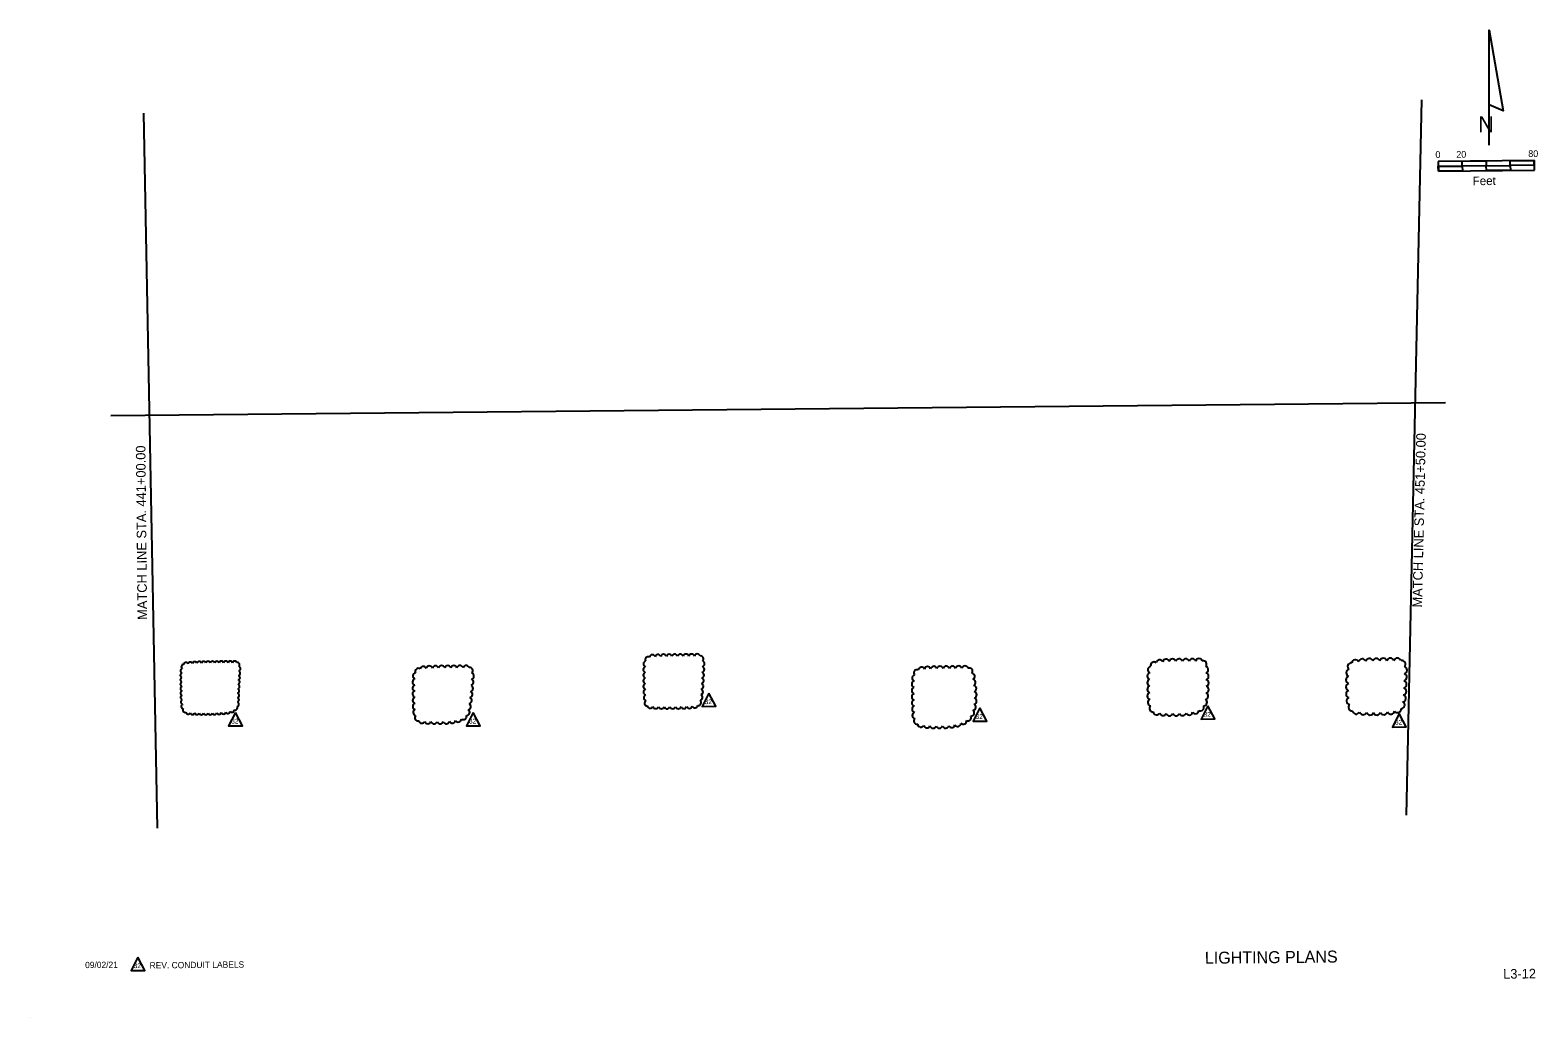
# Model space of a CAD drawing. Extents: x 922408 to 923664, y 636636 to 637460.
import ezdxf

# ---------------------------------------------------------------- set-up
doc = ezdxf.new("R2010")
doc.units = 0
for name, color, linetype in [('ActivePointCell_dp', 7, 'Continuous'), ('AdhocPoint_dp', 7, 'Continuous'), ('Cloud_dp', 7, 'Continuous'), ('MatchLines_dp', 7, 'Continuous'), ('NorthArw_dp', 7, 'Continuous'), ('Scale_dp', 7, 'Continuous'), ('TextLabel', 7, 'Continuous'), ('TextMisc', 7, 'Continuous'), ('TextNotes', 7, 'Continuous'), ('TextShtNo', 7, 'Continuous')]:
    doc.layers.add(name, color=color, linetype=linetype)

msp = doc.modelspace()

# ---------------------------------------------------------------- linework, layer by layer
at = {"layer": 'ActivePointCell_dp'}
msp.add_line((923587.4, 637149.1), (922474.9, 637138.1), dxfattribs=at)
at = {"layer": 'AdhocPoint_dp'}
msp.add_line((922407.6, 636636.3), (922407.6, 636636.3), dxfattribs=at)
at = {"layer": 'Cloud_dp'}
for points in [[(922973.4, 636907), (922967.7, 636895.8), (922979.3, 636896)], [(922578.7, 636890.8), (922573, 636879.6), (922584.6, 636879.7)], [(922776.9, 636890.8), (922771.2, 636879.6), (922782.8, 636879.7)], [(923199.3, 636894.6), (923193.6, 636883.5), (923205.2, 636883.6)], [(923389.3, 636896.5), (923383.7, 636885.3), (923395.2, 636885.5)], [(923548.9, 636889.9), (923543.2, 636878.7), (923554.8, 636878.8)]]:
    msp.add_lwpolyline(points, close=True, dxfattribs=at)
for centre, radius, start, end in [((922535.5, 636928.9), 1.94, 87.0629, 232.0629), ((922537.5, 636930.5), 1.94, 27.4694, 172.4694), ((922541.1, 636931), 1.94, 22.2218, 167.2218), ((922544.8, 636931.2), 1.94, 20.372, 165.372), ((922548.5, 636931.4), 1.94, 19.3363, 164.3363), ((922552.2, 636931.5), 1.94, 18.6507, 163.6507), ((922555.9, 636931.6), 1.94, 18.1729, 163.1729), ((922559.6, 636931.6), 1.94, 18.0695, 163.0695), ((922563.3, 636931.6), 1.94, 18.0695, 163.0695), ((922567, 636931.7), 1.94, 18.0695, 163.0695), ((922570.7, 636931.7), 1.94, 18.0695, 163.0695), ((922574.4, 636931.7), 1.94, 18.0695, 163.0695), ((922578.1, 636931.8), 1.94, 18.0695, 163.0695), ((922580.3, 636930.5), 1.94, 315.3133, 100.3133), ((922581, 636927.3), 1.94, 284.4173, 69.4173), ((922731.2, 636925), 2.68, 56.3128, 201.3128), ((922735.3, 636926.6), 2.68, 22.3621, 167.3621), ((922740.4, 636927), 2.68, 19.9071, 164.9071), ((922745.5, 636927.1), 2.68, 18.7885, 163.7885), ((922750.6, 636927.2), 2.68, 18.1593, 163.1593), ((922755.7, 636927.3), 2.68, 18.0695, 163.0695), ((922760.8, 636927.3), 2.68, 18.0695, 163.0695), ((922765.9, 636927.4), 2.68, 18.0695, 163.0695), ((922771, 636927.4), 2.68, 18.0695, 163.0695), ((922774, 636925.6), 2.68, 314.7185, 99.7185), ((922921.1, 636926.6), 2.46, 106.8525, 251.8525), ((922921.3, 636931.3), 2.46, 105.2115, 250.2115), ((922922.8, 636934.9), 2.46, 64.4078, 209.4078), ((922926.2, 636936.5), 2.46, 21.0985, 166.0985), ((922930.9, 636936.7), 2.46, 19.421, 164.421), ((922935.6, 636936.9), 2.46, 18.6886, 163.6886), ((922940.3, 636936.9), 2.46, 18.2508, 163.2508), ((922944.9, 636937), 2.46, 18.0699, 163.0699), ((922949.6, 636937), 2.46, 18.0695, 163.0695), ((922954.3, 636937.1), 2.46, 18.0695, 163.0695), ((922959, 636937.1), 2.46, 18.0695, 163.0695), ((922963.7, 636937.2), 2.46, 18.0695, 163.0695), ((922966.5, 636935.5), 2.46, 315.3025, 100.3025), ((922967.2, 636926.8), 2.46, 284.525, 69.525), ((922967.4, 636931.5), 2.46, 284.525, 69.525), ((923150.6, 636925.9), 2.73, 24.6638, 169.6638), ((923155.7, 636926.4), 2.73, 20.7187, 165.7187), ((923160.9, 636926.6), 2.73, 19.1288, 164.1288), ((923166.1, 636926.7), 2.73, 18.2398, 163.2398), ((923171.3, 636926.8), 2.73, 18.0695, 163.0695), ((923176.5, 636926.8), 2.73, 18.0695, 163.0695), ((923181.7, 636926.9), 2.73, 18.0695, 163.0695), ((923186.9, 636926.9), 2.73, 18.0695, 163.0695), ((923190.5, 636925.2), 2.73, 326.4662, 111.4662), ((923342.2, 636926.5), 2.88, 100.4246, 245.4246), ((923344.5, 636930.1), 2.88, 50.3955, 195.3955), ((923349.2, 636931.9), 2.88, 25.5069, 170.5069), ((923354.6, 636932.4), 2.88, 21.0103, 166.0103), ((923360, 636932.6), 2.88, 18.8039, 163.8039), ((923365.5, 636932.7), 2.88, 18.0695, 163.0695), ((923371, 636932.8), 2.88, 18.0695, 163.0695), ((923376.5, 636932.8), 2.88, 18.0695, 163.0695), ((923382, 636932.9), 2.88, 18.0695, 163.0695), ((923385.5, 636931), 2.88, 320.4892, 105.4892), ((923386.9, 636926.4), 2.88, 289.0567, 74.0567), ((923509, 636929.1), 3.08, 83.8725, 228.8725), ((923512.4, 636931.8), 3.08, 28.1171, 173.1171), ((923518.1, 636932.5), 3.08, 21.4569, 166.4569), ((923524, 636932.8), 3.08, 19.1108, 164.1108), ((923529.8, 636932.9), 3.08, 18.1025, 163.1025), ((923535.7, 636933), 3.08, 18.0695, 163.0695), ((923541.6, 636933.1), 3.08, 18.0695, 163.0695), ((923547.4, 636933.1), 3.08, 18.0695, 163.0695), ((923551.1, 636931.1), 3.08, 317.9117, 102.9117), ((923552.4, 636926.1), 3.08, 286.0769, 71.0769), ((922534.7, 636921.8), 1.94, 106.9984, 251.9984), ((922534.7, 636918.1), 1.94, 107.5151, 252.5151), ((922534.7, 636914.4), 1.94, 107.8364, 252.8364), ((922534.8, 636925.5), 1.94, 105.9338, 250.9338), ((922580.4, 636916.2), 1.94, 284.4873, 69.4873), ((922580.6, 636919.9), 1.94, 284.4173, 69.4173), ((922580.8, 636923.6), 1.94, 284.4173, 69.4173), ((922729, 636916.3), 2.68, 105.9561, 250.9561), ((922729.3, 636921.4), 2.68, 102.8043, 247.8043), ((922774.5, 636916.1), 2.68, 283.0743, 68.0743), ((922774.9, 636921.2), 2.68, 283.0743, 68.0743), ((922921.1, 636921.9), 2.46, 107.5831, 252.5831), ((922921.1, 636917.2), 2.46, 108.0232, 253.0232), ((922966.4, 636912.7), 2.46, 283.8375, 68.8375), ((922966.7, 636917.4), 2.46, 284.4222, 69.4222), ((922966.9, 636922.1), 2.46, 284.525, 69.525), ((923145.3, 636914.4), 2.73, 106.2708, 251.2708), ((923145.5, 636919.5), 2.73, 103.7063, 248.7063), ((923147, 636923.8), 2.73, 72.1138, 217.1138), ((923192.3, 636921), 2.73, 295.6288, 80.6288), ((923193, 636915.9), 2.73, 295.6229, 80.6229), ((923341.7, 636915.6), 2.88, 107.1286, 252.1286), ((923341.8, 636921.1), 2.88, 105.3798, 250.3798), ((923387.1, 636920.9), 2.88, 289.0567, 74.0567), ((923387.2, 636915.4), 2.88, 288.4493, 73.4493), ((923507.6, 636918), 3.08, 106.8359, 251.8359), ((923507.6, 636912.1), 3.08, 107.9915, 252.9915), ((923507.8, 636923.8), 3.08, 104.566, 249.566), ((923552, 636914.3), 3.08, 285.8129, 70.8129), ((923552.2, 636920.2), 3.08, 286.0769, 71.0769), ((922534.8, 636910.7), 1.94, 108.1083, 253.1083), ((922534.8, 636907), 1.94, 108.7391, 253.7391), ((922534.9, 636903.3), 1.94, 109.7201, 254.7201), ((922579.8, 636901.4), 1.94, 286.1019, 71.1019), ((922579.9, 636905.1), 1.94, 285.4276, 70.4276), ((922580, 636908.8), 1.94, 285.0052, 70.0052), ((922580.2, 636912.5), 1.94, 284.7085, 69.7085), ((922729, 636911.3), 2.68, 107.2485, 252.2485), ((922729, 636906.2), 2.68, 107.9993, 252.9993), ((922729.1, 636901), 2.68, 108.5889, 253.5889), ((922773.1, 636900.9), 2.68, 280.7005, 65.7005), ((922773.7, 636905.9), 2.68, 281.9413, 66.9413), ((922774.1, 636911), 2.68, 282.8, 67.8), ((922921.2, 636912.6), 2.46, 108.4052, 253.4052), ((922921.3, 636907.9), 2.46, 108.9878, 253.9878), ((922921.5, 636903.2), 2.46, 110.1437, 255.1437), ((922965.6, 636903.4), 2.46, 280.9058, 65.9058), ((922966.1, 636908.1), 2.46, 282.8585, 67.8585), ((923145.2, 636909.2), 2.73, 107.447, 252.447), ((923145.3, 636904), 2.73, 108.1185, 253.1185), ((923193.7, 636910.7), 2.73, 293.4763, 78.4763), ((923193.9, 636900.5), 2.73, 283.5714, 68.5714), ((923194, 636905.6), 2.73, 289.0257, 74.0257), ((923341.7, 636910.1), 2.88, 108.1889, 253.1889), ((923341.8, 636904.7), 2.88, 109.7103, 254.7103), ((923386.8, 636904.5), 2.88, 281.4482, 66.4482), ((923387.2, 636909.9), 2.88, 285.8586, 70.8586), ((923507.7, 636906.3), 3.08, 109.7269, 254.7269), ((923508.1, 636900.5), 3.08, 113.362, 258.362), ((923551.4, 636902.7), 3.08, 282.0486, 67.0486), ((923551.8, 636908.5), 3.08, 284.5338, 69.5338), ((922535.1, 636899.6), 1.94, 111.3179, 256.3179), ((922535.5, 636895.9), 1.94, 114.7013, 259.7013), ((922536.7, 636892.9), 1.94, 143.5112, 288.5112), ((922539.2, 636891.4), 1.94, 191.1852, 336.1852), ((922542.9, 636891.1), 1.94, 194.8482, 339.8482), ((922546.6, 636891), 1.94, 196.2339, 341.2339), ((922550.3, 636890.9), 1.94, 197.0255, 342.0255), ((922554, 636890.9), 1.94, 197.5548, 342.5548), ((922557.7, 636890.9), 1.94, 197.9472, 342.9472), ((922561.3, 636891), 1.94, 199.0161, 344.0161), ((922565, 636891.2), 1.94, 200.9785, 345.9785), ((922568.7, 636891.5), 1.94, 203.8098, 348.8098), ((922572.3, 636892), 1.94, 208.3828, 353.3828), ((922575.8, 636893), 1.94, 217.4828, 2.4828), ((922578.5, 636894.8), 1.94, 245.0148, 30.0148), ((922579.7, 636897.7), 1.94, 286.0132, 71.0132), ((922729.2, 636895.9), 2.68, 109.4949, 254.4949), ((922729.5, 636890.9), 2.68, 111.4286, 256.4286), ((922771.3, 636891), 2.68, 269.6993, 54.6993), ((922772.4, 636895.8), 2.68, 278.6931, 63.6931), ((922922.2, 636898.7), 2.46, 122.7796, 267.7796), ((922924.5, 636896.8), 2.46, 191.4246, 336.4246), ((922929.1, 636896.5), 2.46, 195.7196, 340.7196), ((922933.8, 636896.4), 2.46, 196.9732, 341.9732), ((922938.5, 636896.3), 2.46, 197.6498, 342.6498), ((922943.2, 636896.4), 2.46, 198.0921, 343.0921), ((922947.9, 636896.4), 2.46, 198.5188, 343.5188), ((922952.5, 636896.5), 2.46, 199.1633, 344.1633), ((922957.2, 636896.7), 2.46, 200.3507, 345.3507), ((922961.8, 636897.1), 2.46, 204.2961, 349.2961), ((922964.5, 636899.1), 2.46, 265.0733, 50.0733), ((923145.3, 636898.8), 2.73, 108.5861, 253.5861), ((923145.5, 636893.6), 2.73, 109.3213, 254.3213), ((923145.7, 636888.4), 2.73, 110.8911, 255.8911), ((923191.9, 636890.6), 2.73, 267.3896, 52.3896), ((923193.3, 636895.4), 2.73, 276.889, 61.889), ((923342.2, 636899.2), 2.88, 112.8098, 257.8098), ((923343.5, 636894.3), 2.88, 131.5815, 276.5815), ((923346.7, 636891.7), 2.88, 186.8319, 331.8319), ((923352, 636891.1), 2.88, 194.2513, 339.2513), ((923357.5, 636890.9), 2.88, 196.6657, 341.6657), ((923362.9, 636890.9), 2.88, 198.1238, 343.1238), ((923368.4, 636891.1), 2.88, 200.6609, 345.6609), ((923373.8, 636891.6), 2.88, 205.0341, 350.0341), ((923379, 636892.7), 2.88, 213.8707, 358.8707), ((923383.3, 636895.1), 2.88, 240.9822, 25.9822), ((923385.8, 636899.3), 2.88, 271.9345, 56.9345), ((923509.6, 636895.2), 3.08, 131.5163, 276.5163), ((923513, 636892.6), 3.08, 188.5265, 333.5265), ((923518.7, 636892), 3.08, 195.0782, 340.0782), ((923524.5, 636891.8), 3.08, 197.0087, 342.0087), ((923530.4, 636891.8), 3.08, 198.1564, 343.1564), ((923536.2, 636892), 3.08, 200.0636, 345.0636), ((923542, 636892.5), 3.08, 203.8682, 348.8682), ((923547.5, 636893.8), 3.08, 218.6655, 3.6655), ((923550.4, 636897.1), 3.08, 272.7475, 57.7475), ((922730.9, 636886.5), 2.68, 139.4, 284.4), ((922734.2, 636884.5), 2.68, 191.4099, 336.4099), ((922739.2, 636884.1), 2.68, 195.4252, 340.4252), ((922744.3, 636884), 2.68, 196.9867, 341.9867), ((922749.4, 636884), 2.68, 197.9459, 342.9459), ((922754.5, 636884.1), 2.68, 200.3489, 345.3489), ((922759.5, 636884.6), 2.68, 204.7889, 349.7889), ((922764.4, 636885.5), 2.68, 212.7963, 357.7963), ((922768.7, 636887.6), 2.68, 231.8265, 16.8265), ((923147, 636883.8), 2.73, 134.8495, 279.8495), ((923150.1, 636881.4), 2.73, 185.999, 330.999), ((923155.2, 636880.7), 2.73, 193.1464, 338.1464), ((923160.3, 636880.4), 2.73, 195.9476, 340.9476), ((923165.5, 636880.4), 2.73, 197.5603, 342.5603), ((923170.7, 636880.5), 2.73, 200.1629, 345.1629), ((923175.8, 636880.9), 2.73, 204.8584, 349.8584), ((923180.8, 636881.9), 2.73, 211.9727, 356.9727), ((923185.5, 636883.7), 2.73, 223.7459, 8.7459), ((923189.4, 636886.5), 2.73, 243.8345, 28.8345)]:
    msp.add_arc(centre, radius, start, end, dxfattribs=at)
at = {"layer": 'MatchLines_dp'}
for p, q in [((923567.5, 637401.5), (923554.8, 636805.3)), ((922502.2, 637390.5), (922513.5, 636794.5))]:
    msp.add_line(p, q, dxfattribs=at)
at = {"layer": 'NorthArw_dp'}
msp.add_line((923624, 637363.7), (923624, 637459.7), dxfattribs=at)
msp.add_lwpolyline([(923624, 637397.3), (923624, 637459.7), (923635.5, 637392.5)], close=True, dxfattribs=at)
at = {"layer": 'Scale_dp'}
for p, q in [((923661.5, 637351), (923581.5, 637350.2)), ((923581.5, 637350.2), (923581.6, 637342.2)), ((923581.6, 637342.2), (923661.6, 637343)), ((923661.6, 637343), (923661.5, 637351))]:
    msp.add_line(p, q, dxfattribs=at)
for points in [[(923581.6, 637342.2), (923581.5, 637346.2), (923601.5, 637346.4), (923601.6, 637342.4)], [(923601.5, 637346.4), (923601.5, 637350.4), (923621.5, 637350.6), (923621.5, 637346.6)], [(923621.6, 637342.6), (923621.5, 637346.6), (923641.5, 637346.8), (923641.6, 637342.8)], [(923641.5, 637346.8), (923641.5, 637350.8), (923661.5, 637351), (923661.5, 637347)]]:
    msp.add_lwpolyline(points, close=True, dxfattribs=at)
at = {"layer": 'TextNotes'}
msp.add_lwpolyline([(922497.3, 636686.8), (922491.7, 636675.7), (922503.2, 636675.8)], close=True, dxfattribs=at)

# ---------------------------------------------------------------- texts
at = {"layer": 'Cloud_dp'}
for p in [(922969.9, 636897.8), (923385.8, 636887.3), (922575.2, 636881.6), (922773.4, 636881.6), (923195.8, 636885.5), (923545.4, 636880.7)]:
    msp.add_text('32', height=3.94, rotation=0.5695, dxfattribs=at).set_placement(p)
at = {"layer": 'MatchLines_dp'}
for s, rotation, p in [('MATCH LINE STA. 451+50.00', 88.725, (923567.9, 636978.3)), ('MATCH LINE STA. 441+00.00', 90.5695, (922505.1, 636968.1))]:
    msp.add_text(s, height=8, rotation=rotation, dxfattribs=at).set_placement(p)
at = {"layer": 'NorthArw_dp'}
msp.add_text('N', height=13.4, dxfattribs=at).set_placement((923614.8, 637374.5))
at = {"layer": 'Scale_dp'}
for s, height, p in [('0', 5.6, (923579.1, 637353.1)), ('20', 5.6, (923596.5, 637353.3)), ('80', 5.6, (923656.5, 637353.9)), ('Feet', 7.2, (923610.2, 637330.4))]:
    msp.add_text(s, height=height, rotation=0.5695, dxfattribs=at).set_placement(p)
at = {"layer": 'TextLabel'}
for s, p in [('09/02/21', (922453.4, 636677.7)), ('REV. CONDUIT LABELS', (922507.2, 636677.4))]:
    msp.add_text(s, height=5.25, rotation=0.5695, dxfattribs=at).set_placement(p)
at = {"layer": 'TextMisc'}
msp.add_text('        LIGHTING PLANS         ', height=10, rotation=0.5695, dxfattribs=at).set_placement((923357.2, 636681))
at = {"layer": 'TextNotes'}
msp.add_text('32', height=3.94, rotation=0.5695, dxfattribs=at).set_placement((922493.9, 636677.7))
at = {"layer": 'TextShtNo'}
msp.add_text('L3-12 ', height=8, rotation=0.5695, dxfattribs=at).set_placement((923635.6, 636668.9))

doc.saveas('drawing.dxf')
